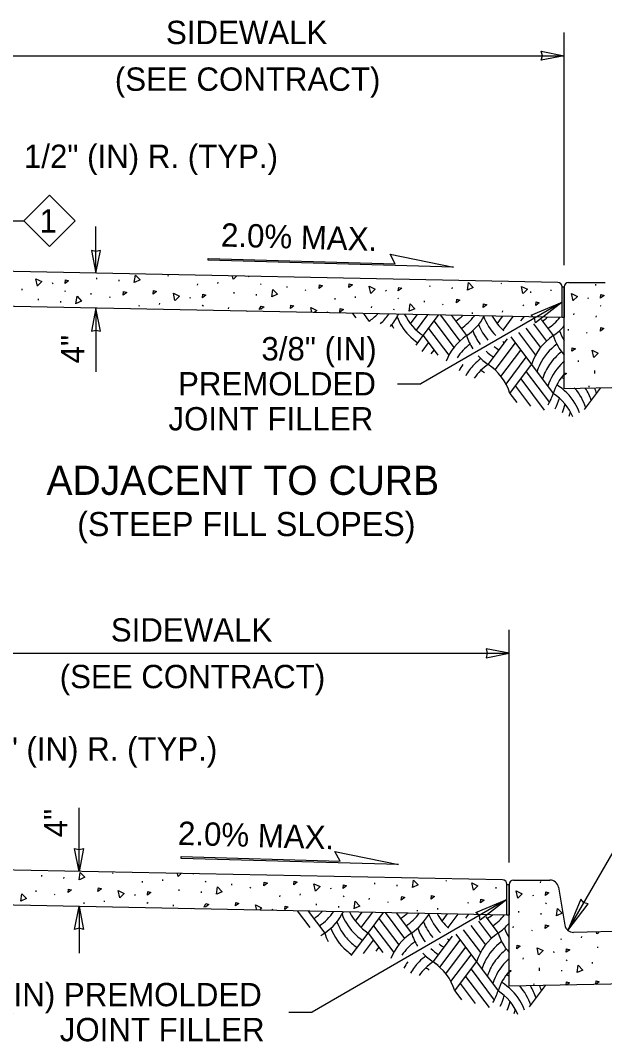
# Model space of a CAD drawing. Extents: x 99862 to 103151, y 100000 to 102076.
# Drawn here: x 100381 to 100781, y 100969 to 101669 of the extents above; entities that cross this region are included whole.
import ezdxf

# ---------------------------------------------------------------- set-up
doc = ezdxf.new("R2010")
doc.units = 0
for name, color, linetype in [('Level 13', 7, 'Continuous'), ('Level 15', 7, 'Continuous'), ('Level 16', 7, 'Continuous'), ('Level 20', 7, 'Continuous'), ('Level 34', 7, 'Continuous'), ('Level 6', 7, 'Continuous')]:
    doc.layers.add(name, color=color, linetype=linetype)

msp = doc.modelspace()

# ---------------------------------------------------------------- linework, layer by layer
at = {"layer": 'Level 13'}
for p, q in [((100433.45, 101491.66), (100433.51, 101492.53)), ((100448.71, 101490.21), (100448.78, 101491.08)), ((100481.98, 101494.1), (100482.5, 101493.72)), ((100537.22, 101493.5), (100537.42, 101493.09)), ((100382.36, 101484.02), (100382.42, 101484.9)), ((100402.96, 101489.15), (100403.32, 101488.43)), ((100411.41, 101483.64), (100411.93, 101483.26)), ((100502.53, 101487.5), (100502.59, 101488.37)), ((100516.46, 101488.69), (100516.52, 101489.56)), ((100545.52, 101488.3), (100546.04, 101487.93)), ((100563.74, 101485.76), (100563.8, 101486.63)), ((100576.11, 101484.21), (100576.63, 101483.83)), ((100631.19, 101483.93), (100631.55, 101483.21)), ((100661.68, 101486.44), (100661.74, 101487.31)), ((100676.95, 101484.99), (100677.01, 101485.87)), ((100710.22, 101488.88), (100710.74, 101488.5)), ((100730.77, 101482.28), (100730.83, 101483.15)), ((100744.7, 101483.47), (100744.76, 101484.35)), ((100775.22, 101487.29), (100775.28, 101488.17)), ((100393.47, 101477.11), (100393.53, 101477.98)), ((100408.74, 101475.66), (100408.8, 101476.53)), ((100429.64, 101481.09), (100429.7, 101481.96)), ((100442.01, 101479.55), (100442.53, 101479.17)), ((100497.09, 101479.27), (100497.45, 101478.55)), ((100527.58, 101481.77), (100527.64, 101482.65)), ((100542.85, 101480.33), (100542.91, 101481.2)), ((100596.66, 101477.61), (100596.72, 101478.49)), ((100610.59, 101478.81), (100610.65, 101479.68)), ((100639.65, 101478.42), (100640.17, 101478.04)), ((100657.87, 101475.88), (100657.93, 101476.75)), ((100769.78, 101479.07), (100770.13, 101478.35)), ((100462.56, 101472.95), (100462.62, 101473.82)), ((100476.49, 101474.14), (100476.55, 101475.01)), ((100505.55, 101473.76), (100506.06, 101473.38)), ((100505.95, 101473.69), (100506.47, 101473.31)), ((100523.77, 101471.21), (100523.83, 101472.08)), ((100536.14, 101469.67), (100536.35, 101469.51)), ((100591.22, 101469.38), (100591.58, 101468.66)), ((100621.71, 101471.89), (100621.77, 101472.76)), ((100636.98, 101470.44), (100637.04, 101471.32)), ((100670.25, 101474.33), (100670.76, 101473.95)), ((100711.43, 101468.93), (100711.49, 101469.8)), ((100725.33, 101474.05), (100725.68, 101473.33)), ((100778.23, 101473.56), (100778.75, 101473.18)), ((100690.8, 101467.73), (100690.86, 101468.6)), ((100760.29, 101467.03), (100760.35, 101467.9)), ((100775.56, 101465.58), (100775.62, 101466.45)), ((100756.48, 101456.46), (100756.54, 101457.33)), ((100768.86, 101454.92), (100769.37, 101454.54)), ((100763.36, 101434.96), (100763.42, 101435.83)), ((100774.48, 101426.97), (100774.54, 101428.92)), ((100770.67, 101417.48), (100770.73, 101418.35)), ((100444.22, 101084.59), (100444.74, 101084.21)), ((100499.46, 101083.99), (100499.66, 101083.59)), ((100395.69, 101082.15), (100395.75, 101083.03)), ((100410.95, 101080.71), (100411.02, 101081.58)), ((100464.77, 101077.99), (100464.83, 101078.86)), ((100478.7, 101079.19), (100478.76, 101080.06)), ((100507.76, 101078.8), (100508.28, 101078.42)), ((100525.98, 101076.25), (100526.04, 101077.13)), ((100623.92, 101076.94), (100623.98, 101077.81)), ((100672.46, 101079.38), (100672.98, 101079)), ((100737.46, 101077.79), (100737.52, 101078.66)), ((100391.88, 101071.59), (100391.94, 101072.46)), ((100404.25, 101070.04), (100404.77, 101069.66)), ((100459.33, 101069.76), (100459.69, 101069.04)), ((100489.82, 101072.27), (100489.88, 101073.14)), ((100505.09, 101070.82), (100505.15, 101071.7)), ((100538.36, 101074.71), (100538.87, 101074.33)), ((100572.83, 101069.3), (100572.89, 101070.18)), ((100593.44, 101074.43), (100593.79, 101073.71)), ((100639.19, 101075.49), (100639.25, 101076.36)), ((100706.94, 101073.97), (100707, 101074.84)), ((100424.8, 101063.44), (100424.86, 101064.32)), ((100438.73, 101064.64), (100438.79, 101065.51)), ((100467.79, 101064.25), (100468.3, 101063.87)), ((100468.19, 101064.18), (100468.71, 101063.8)), ((100558.9, 101068.11), (100558.96, 101068.98)), ((100583.95, 101062.39), (100584.01, 101063.26)), ((100602.29, 101068.85), (100602.81, 101068.47)), ((100620.11, 101066.37), (100620.17, 101067.24)), ((100632.49, 101064.83), (100633, 101064.45)), ((100687.57, 101064.55), (100687.92, 101063.83)), ((100732.02, 101069.56), (100732.37, 101068.84)), ((100740.87, 101063.98), (100741.39, 101063.6)), ((100486.01, 101061.71), (100486.07, 101062.58)), ((100498.38, 101060.16), (100498.59, 101060.01)), ((100553.46, 101059.88), (100553.82, 101059.16)), ((100599.22, 101060.94), (100599.28, 101061.81)), ((100653.04, 101058.23), (100653.1, 101059.1)), ((100666.96, 101059.42), (100667.03, 101060.29)), ((100722.53, 101057.52), (100722.59, 101058.39)), ((100737.8, 101056.07), (100737.86, 101056.95)), ((100718.72, 101046.96), (100718.78, 101047.83)), ((100731.1, 101045.41), (100731.61, 101045.03)), ((100751.64, 101038.81), (100751.7, 101039.68)), ((100765.57, 101040.01), (100765.63, 101040.88)), ((100746.2, 101030.58), (100746.56, 101029.86)), ((100776.69, 101033.09), (100776.75, 101033.96)), ((100725.6, 101025.46), (100725.66, 101026.33)), ((100755.06, 101025), (100755.58, 101024.62)), ((100772.88, 101022.53), (100772.94, 101023.4)), ((100736.72, 101017.47), (100736.78, 101019.41)), ((100751.99, 101017.09), (100752.05, 101017.97)), ((100732.91, 101007.98), (100732.97, 101008.85))]:
    msp.add_line(p, q, dxfattribs=at)
for points in [[(100392.82, 101486.86), (100391.75, 101491.87), (100395.86, 101489.87), (100392.89, 101486.91)], [(100411.76, 101488.68), (100412, 101491.13), (100414.12, 101490.48), (100411.76, 101488.68)], [(100459.16, 101489.29), (100459.87, 101494.36), (100463.05, 101491.08), (100459.25, 101489.32)], [(100526.93, 101491.52), (100526.46, 101493.71)], [(100529.08, 101493.66), (100526.99, 101491.58)], [(100451.56, 101480.57), (100451.8, 101483.02), (100453.93, 101482.37), (100451.56, 101480.57)], [(100472.03, 101481.26), (100472.27, 101483.71), (100474.39, 101483.07), (100472.03, 101481.26)], [(100553.3, 101479.41), (100554, 101484.48), (100557.18, 101481.2), (100553.38, 101479.44)], [(100585.67, 101485.23), (100585.91, 101487.68), (100588.03, 101487.04), (100585.67, 101485.23)], [(100606.13, 101485.93), (100606.37, 101488.38), (100608.5, 101487.73), (100606.13, 101485.93)], [(100621.06, 101481.64), (100619.98, 101486.65), (100624.1, 101484.65), (100621.13, 101481.7)], [(100639.99, 101483.46), (100640.23, 101485.91), (100642.36, 101485.27), (100639.99, 101483.46)], [(100687.4, 101484.07), (100688.1, 101489.15), (100691.28, 101485.86), (100687.48, 101484.1)], [(100725.33, 101481.61), (100724.26, 101486.62), (100728.37, 101484.62), (100725.4, 101481.67)], [(100419.19, 101474.74), (100419.9, 101479.81), (100423.08, 101476.53), (100419.27, 101474.77)], [(100486.95, 101476.97), (100485.88, 101481.98), (100489.99, 101479.99), (100487.02, 101477.03)], [(100505.89, 101478.79), (100506.13, 101481.24), (100508.25, 101480.6), (100505.89, 101478.79)], [(100679.8, 101475.35), (100680.04, 101477.8), (100682.16, 101477.16), (100679.8, 101475.35)], [(100734.12, 101473.58), (100734.37, 101476.03), (100736.49, 101475.38), (100734.12, 101473.58)], [(100759.64, 101476.77), (100758.57, 101481.78), (100762.68, 101479.78), (100759.71, 101476.83)], [(100778.57, 101478.59), (100778.81, 101481.04), (100780.94, 101480.4), (100778.57, 101478.59)], [(100544.66, 101470.68), (100545.94, 101473.14), (100548.06, 101472.49), (100545.69, 101470.68)], [(100566.16, 101471.38), (100566.4, 101473.83), (100568.52, 101473.18), (100566.16, 101471.38)], [(100580.76, 101468.62), (100580.01, 101472.1), (100584.12, 101470.1), (100582.6, 101468.59)], [(100600.02, 101468.91), (100600.26, 101471.36), (100602.39, 101470.72), (100600.02, 101468.91)], [(100647.43, 101469.52), (100648.13, 101474.6), (100651.31, 101471.31), (100647.51, 101469.55)], [(100698.17, 101472.23), (100698.42, 101474.68), (100700.54, 101474.04), (100698.17, 101472.23)], [(100778.41, 101455.94), (100778.65, 101458.39), (100780.77, 101457.74), (100778.41, 101455.94)], [(100758.9, 101442.08), (100759.14, 101444.53), (100761.26, 101443.89), (100758.9, 101442.08)], [(100773.83, 101437.79), (100772.75, 101442.8), (100776.86, 101440.8), (100773.89, 101437.85)], [(100753.65, 101427.33), (100755.15, 101426.87), (100753.65, 101425.72)], [(100421.4, 101079.78), (100422.11, 101084.86), (100425.29, 101081.58), (100421.49, 101079.81)], [(100489.17, 101082.02), (100488.7, 101084.21)], [(100491.32, 101084.15), (100489.24, 101082.07)], [(100547.91, 101075.73), (100548.15, 101078.18), (100550.27, 101077.54), (100547.91, 101075.73)], [(100568.37, 101076.42), (100568.61, 101078.87), (100570.74, 101078.23), (100568.37, 101076.42)], [(100583.3, 101072.14), (100582.22, 101077.15), (100586.34, 101075.15), (100583.37, 101072.19)], [(100649.64, 101074.57), (100650.34, 101079.64), (100653.52, 101076.36), (100649.72, 101074.6)], [(100691.52, 101072.74), (100690.44, 101077.75), (100694.55, 101075.75), (100691.59, 101072.79)], [(100381.43, 101065.24), (100382.14, 101070.31), (100385.32, 101067.03), (100381.51, 101065.27)], [(100413.8, 101071.06), (100414.04, 101073.51), (100416.17, 101072.87), (100413.8, 101071.06)], [(100434.27, 101071.76), (100434.51, 101074.21), (100436.63, 101073.56), (100434.27, 101071.76)], [(100449.2, 101067.47), (100448.12, 101072.48), (100452.23, 101070.48), (100449.26, 101067.53)], [(100468.13, 101069.29), (100468.37, 101071.74), (100470.49, 101071.1), (100468.13, 101069.29)], [(100515.54, 101069.9), (100516.24, 101074.98), (100519.42, 101071.69), (100515.62, 101069.93)], [(100602.23, 101073.96), (100602.47, 101076.41), (100604.6, 101075.76), (100602.23, 101073.96)], [(100721.88, 101067.27), (100720.81, 101072.28), (100724.92, 101070.28), (100721.95, 101067.33)], [(100740.81, 101069.09), (100741.05, 101071.54), (100743.18, 101070.9), (100740.81, 101069.09)], [(100506.9, 101061.18), (100508.18, 101063.63), (100510.3, 101062.99), (100507.93, 101061.18)], [(100528.4, 101061.87), (100528.64, 101064.32), (100530.76, 101063.68), (100528.4, 101061.87)], [(100609.67, 101060.02), (100610.37, 101065.09), (100613.55, 101061.81), (100609.75, 101060.05)], [(100642.04, 101065.85), (100642.28, 101068.3), (100644.41, 101067.65), (100642.04, 101065.85)], [(100662.5, 101066.54), (100662.74, 101068.99), (100664.87, 101068.35), (100662.5, 101066.54)], [(100696.36, 101064.07), (100696.61, 101066.52), (100698.73, 101065.88), (100696.36, 101064.07)], [(100543, 101059.12), (100542.25, 101062.6), (100546.36, 101060.6), (100544.84, 101059.08)], [(100562.26, 101059.41), (100562.5, 101061.86), (100564.63, 101061.21), (100562.26, 101059.41)], [(100748.25, 101055.15), (100748.95, 101060.23), (100752.13, 101056.94), (100748.33, 101055.18)], [(100740.65, 101046.43), (100740.89, 101048.88), (100743.01, 101048.24), (100740.65, 101046.43)], [(100776.04, 101042.84), (100775.77, 101044.11)], [(100777.36, 101044.14), (100776.11, 101042.89)], [(100721.14, 101032.58), (100721.38, 101035.03), (100723.51, 101034.38), (100721.14, 101032.58)], [(100736.07, 101028.29), (100734.99, 101033.3), (100739.1, 101031.3), (100736.14, 101028.35)], [(100755, 101030.11), (100755.24, 101032.56), (100757.37, 101031.92), (100755, 101030.11)], [(100762.44, 101016.17), (100763.14, 101021.25), (100766.32, 101017.96), (100762.52, 101016.2)], [(100715.89, 101017.82), (100717.39, 101017.37), (100715.89, 101016.22)], [(100754.86, 101007.69), (100755.08, 101009.9), (100757.2, 101009.26), (100755.16, 101007.7)], [(100775.3, 101008.14), (100775.54, 101010.6), (100777.66, 101009.95), (100775.3, 101008.14)]]:
    msp.add_lwpolyline(points, dxfattribs=at)
at = {"layer": 'Level 15'}
for p, q in [((100753.65, 101501.2), (100753.65, 101660.69)), ((100322.4, 101644.67), (100753.65, 101644.67)), ((100367.51, 101531.52), (100383.51, 101531.52)), ((100432.85, 101495.58), (100432.85, 101527.58)), ((100752.15, 101475.72), (100655.37, 101419.85)), ((100432.85, 101471.58), (100432.85, 101427.98)), ((100639.37, 101419.85), (100655.37, 101419.85)), ((100715.89, 101091.69), (100715.89, 101251.18)), ((100284.64, 101235.17), (100715.89, 101235.17)), ((100421.33, 101085.56), (100421.33, 101129.16)), ((100756.12, 101045.18), (100802.54, 101125.58)), ((100714.39, 101066.22), (100580.92, 100989.16)), ((100421.32, 101061.56), (100421.32, 101029.56)), ((100564.92, 100989.16), (100580.92, 100989.16))]:
    msp.add_line(p, q, dxfattribs=at)
for points in [[(100753.65, 101644.67), (100737.93, 101641.59), (100738.65, 101644.67), (100737.93, 101647.76)], [(100432.84, 101495.58), (100435.93, 101511.31), (100432.84, 101510.58), (100429.76, 101511.31)], [(100752.15, 101475.72), (100733.87, 101461.72), (100733.29, 101464.84), (100730.89, 101466.89)], [(100432.85, 101471.58), (100429.76, 101455.86), (100432.85, 101456.59), (100435.93, 101455.86)], [(100715.89, 101235.17), (100700.16, 101238.25), (100700.89, 101235.17), (100700.16, 101232.08)], [(100421.32, 101085.56), (100418.24, 101101.28), (100421.32, 101100.55), (100424.41, 101101.28)], [(100714.39, 101066.22), (100696.11, 101052.22), (100695.53, 101055.33), (100693.13, 101057.39)], [(100756.12, 101045.18), (100770.12, 101063.46), (100767.01, 101064.03), (100764.95, 101066.44)], [(100421.32, 101061.56), (100424.41, 101045.83), (100421.32, 101046.56), (100418.24, 101045.83)]]:
    msp.add_lwpolyline(points, close=True, dxfattribs=at)
at = {"layer": 'Level 16'}
for points in [[(100752.15, 101486.2), (100753.65, 101486.2), (100753.65, 101465.2), (100752.15, 101465.2)], [(100714.39, 101076.69), (100715.89, 101076.69), (100715.89, 101055.69), (100714.39, 101055.69)]]:
    msp.add_lwpolyline(points, close=True, dxfattribs=at)
at = {"layer": 'Level 20'}
for points in [[(100401.07, 101549.08), (100418.62, 101531.52), (100401.07, 101513.97), (100383.51, 101531.52)], [(100509.82, 101505.81), (100637.87, 101502.11), (100634.32, 101508.7), (100677.83, 101499.72), (100509.78, 101504.58)], [(100491.19, 101095.76), (100600.11, 101092.61), (100596.56, 101099.19), (100640.07, 101090.22), (100491.15, 101094.52)]]:
    msp.add_lwpolyline(points, close=True, dxfattribs=at)
at = {"layer": 'Level 34'}
for p, q in [((100608.5, 101468.07), (100610.8, 101465)), ((100616.04, 101467.92), (100619.83, 101462.87)), ((100648.3, 101461.01), (100652.93, 101467.18)), ((100652.38, 101456.55), (100660.24, 101467.04)), ((100657.03, 101452.85), (100667.56, 101466.89)), ((100664.46, 101462.75), (100678, 101444.7)), ((100668.8, 101466.86), (100682.08, 101449.16)), ((100676.34, 101466.71), (100686.73, 101452.85)), ((100707.7, 101461.01), (100711.45, 101466.01)), ((100711.77, 101456.55), (100718.76, 101465.86)), ((100723.98, 101462.93), (100726.08, 101465.72)), ((100737.79, 101463.97), (100746.13, 101452.85)), ((100660.75, 101457.8), (100674.56, 101439.39)), ((100722.25, 101455), (100733.95, 101439.39)), ((100727.43, 101457.99), (100737.4, 101444.7)), ((100732.61, 101460.98), (100741.47, 101449.16)), ((100652.2, 101446.41), (100657.03, 101452.85)), ((100656.3, 101441.98), (100660.75, 101447.91)), ((100657.03, 101452.85), (100667.14, 101439.38)), ((100701.58, 101433.05), (100714.82, 101450.71)), ((100706.23, 101429.36), (100720.14, 101447.9)), ((100717.07, 101452.01), (100731.28, 101433.06)), ((100662.55, 101440.42), (100664.46, 101442.96)), ((100710.31, 101424.9), (100723.85, 101442.95)), ((100713.76, 101419.59), (100727.57, 101438)), ((100716.43, 101413.26), (100731.28, 101433.05)), ((100727.57, 101428.11), (100743.46, 101406.92)), ((100731.28, 101433.06), (100746.13, 101413.26)), ((100723.86, 101423.16), (100739.92, 101401.74)), ((100716.44, 101413.26), (100721.12, 101407.01)), ((100720.15, 101418.21), (100730.41, 101404.52)), ((100767.61, 101402.31), (100775.83, 101413.26)), ((100775.83, 101413.26), (100778.57, 101416.92)), ((100570.74, 101058.57), (100579.35, 101047.09)), ((100578.28, 101058.42), (100589.58, 101043.35)), ((100610.54, 101051.51), (100615.17, 101057.68)), ((100614.62, 101047.04), (100622.48, 101057.53)), ((100619.27, 101043.35), (100629.8, 101057.38)), ((100631.04, 101057.36), (100644.32, 101039.66)), ((100638.58, 101057.21), (100648.97, 101043.35)), ((100669.94, 101051.51), (100673.69, 101056.51)), ((100674.02, 101047.04), (100681, 101056.36)), ((100686.22, 101053.42), (100688.32, 101056.21)), ((100626.7, 101053.25), (100640.24, 101035.19)), ((100694.85, 101051.48), (100703.71, 101039.66)), ((100700.03, 101054.47), (100708.37, 101043.35)), ((100607.68, 101027.89), (100619.27, 101043.35)), ((100619.27, 101043.35), (100629.38, 101029.88)), ((100622.99, 101048.3), (100636.8, 101029.89)), ((100679.31, 101042.5), (100693.52, 101023.55)), ((100684.49, 101045.49), (100696.19, 101029.89)), ((100689.67, 101048.48), (100699.64, 101035.19)), ((100616.24, 101029.4), (100622.99, 101038.4)), ((100663.82, 101023.55), (100677.06, 101041.2)), ((100668.48, 101019.86), (100682.38, 101038.4)), ((100624.79, 101030.91), (100626.7, 101033.45)), ((100672.55, 101015.39), (100686.09, 101033.45)), ((100676, 101010.08), (100689.81, 101028.5)), ((100678.67, 101003.75), (100693.52, 101023.55)), ((100693.52, 101023.55), (100708.37, 101003.75)), ((100689.81, 101018.6), (100705.7, 100997.42)), ((100682.39, 101008.7), (100692.65, 100995.02)), ((100686.1, 101013.65), (100702.16, 100992.23)), ((100738.07, 101003.75), (100740.81, 101007.41)), ((100678.68, 101003.75), (100683.37, 100997.5)), ((100729.85, 100992.8), (100738.07, 101003.75))]:
    msp.add_line(p, q, dxfattribs=at)
for centre, start, end in [((100598.95, 101493.94), 303.90361, 315.75237), ((100602.66, 101488.99), 311.83361, 325.24141), ((100606.37, 101484.04), 318.61621, 333.77581), ((100674.28, 101479.09), 200.87781, 211.33197), ((100677.99, 101484.04), 206.36846, 236.09639), ((100658.35, 101493.94), 303.90361, 313.21892), ((100662.06, 101488.99), 303.90361, 323.03823), ((100665.77, 101484.04), 303.90361, 331.76223), ((100733.68, 101479.09), 199.94587, 224.0978), ((100737.39, 101484.04), 208.43007, 227.95518), ((100717.74, 101493.94), 303.90361, 310.56526), ((100721.45, 101488.99), 303.90361, 320.77209), ((100670.57, 101474.14), 201.43438, 205.44713), ((100674.28, 101479.09), 211.33188, 236.09639), ((100726.26, 101469.19), 200.24322, 216.55794), ((100729.97, 101474.14), 201.43438, 220.3049), ((100725.17, 101484.04), 303.90361, 319.2878), ((100785.65, 101469.19), 200.24322, 211.61888), ((100707.69, 101421.67), 123.90361, 158.72507), ((100722.54, 101464.24), 197.6434, 212.83994), ((100733.68, 101479.09), 233.78139, 236.09639), ((100767.09, 101421.67), 123.90361, 162.3566), ((100781.94, 101464.24), 197.6434, 221.1697), ((100711.4, 101416.72), 126.30625, 146.15458), ((100726.26, 101469.19), 225.89517, 236.09368), ((100729.97, 101474.14), 229.78975, 236.09639), ((100770.8, 101416.72), 126.30625, 154.2266), ((100774.51, 101411.77), 127.1006, 145.49109), ((100718.83, 101406.82), 126.331, 135.71278), ((100722.54, 101464.24), 222.07643, 236.09645), ((100722.54, 101464.24), 222.07643, 236.09645), ((100778.23, 101406.82), 130.84176, 135.71278), ((100715.12, 101411.77), 145.49102, 153.1583), ((100718.83, 101406.82), 135.71269, 150.41204), ((100722.54, 101401.87), 123.90361, 144.38269), ((100676.91, 101396.92), 54.12975, 58.54646), ((100680.62, 101401.87), 49.65764, 56.09634), ((100680.62, 101401.87), 17.6434, 56.09634), ((100770.8, 101416.72), 154.22654, 162.3566), ((100774.51, 101411.77), 145.49102, 162.3566), ((100778.23, 101406.82), 135.71269, 162.3566), ((100781.94, 101401.87), 138.8303, 162.3566), ((100732.59, 101391.97), 56.30046, 59.30215), ((100710.32, 101424.65), 329.02899, 342.3566), ((100725.17, 101382.07), 23.54417, 56.09639), ((100728.88, 101387.02), 31.33163, 58.48737), ((100732.59, 101391.97), 40.94134, 41.44048), ((100732.59, 101391.97), 17.6434, 40.94141), ((100736.3, 101396.92), 17.6434, 31.78143), ((100740.02, 101401.87), 17.6434, 23.47063), ((100714.03, 101419.7), 333.0258, 345.01126), ((100717.74, 101414.75), 337.02798, 346.31988), ((100728.88, 101387.02), 20.26046, 31.33172), ((100721.45, 101409.8), 341.05532, 345.77133), ((100561.19, 101084.44), 303.90361, 315.75237), ((100564.9, 101079.49), 303.90361, 325.24141), ((100568.62, 101074.54), 303.90361, 333.77581), ((100636.52, 101069.59), 200.87781, 211.33197), ((100640.23, 101074.54), 206.36846, 236.09639), ((100620.59, 101084.44), 303.90361, 313.21892), ((100624.3, 101079.49), 303.90361, 323.03823), ((100628.01, 101074.54), 303.90361, 331.76223), ((100695.92, 101069.59), 199.94587, 224.0978), ((100699.63, 101074.54), 208.43007, 227.95518), ((100679.98, 101084.44), 303.90361, 310.56526), ((100683.69, 101079.49), 303.90361, 320.77209), ((100632.81, 101064.64), 201.43438, 220.94161), ((100636.52, 101069.59), 211.33188, 236.09639), ((100692.21, 101064.64), 201.43438, 220.3049), ((100687.41, 101074.54), 303.90361, 319.2878), ((100610.54, 101012.16), 123.90361, 128.99779), ((100625.39, 101054.74), 197.6434, 207.3316), ((100629.1, 101059.69), 200.24322, 228.95992), ((100669.93, 101012.16), 123.90361, 158.72507), ((100684.78, 101054.74), 197.6434, 212.83994), ((100688.5, 101059.69), 200.24322, 216.55794), ((100729.33, 101012.16), 123.90361, 162.3566), ((100744.18, 101054.74), 197.6434, 221.1697), ((100747.89, 101059.69), 200.24322, 211.61888), ((100614.25, 101007.21), 126.30625, 126.31242), ((100632.81, 101064.64), 220.94154, 236.09639), ((100673.64, 101007.21), 126.30625, 146.15458), ((100692.21, 101064.64), 229.78975, 236.09639), ((100695.92, 101069.59), 233.78139, 236.09639), ((100733.04, 101007.21), 126.30625, 154.2266), ((100629.1, 101059.69), 228.95986, 236.09639), ((100684.78, 101054.74), 222.07643, 236.09645), ((100684.78, 101054.74), 222.07643, 236.09645), ((100688.5, 101059.69), 225.89517, 236.09368), ((100736.75, 101002.26), 127.1006, 145.49109), ((100677.36, 101002.26), 145.49102, 153.1583), ((100681.07, 100997.31), 135.71269, 150.41204), ((100681.07, 100997.31), 126.331, 135.71278), ((100684.78, 100992.36), 123.90361, 144.38269), ((100642.86, 100992.36), 49.65764, 56.09634), ((100642.86, 100992.36), 17.6434, 56.09634), ((100733.04, 101007.21), 154.22654, 162.3566), ((100736.75, 101002.26), 145.49102, 162.3566), ((100740.47, 100997.31), 135.71269, 162.3566), ((100740.47, 100997.31), 130.84176, 135.71278), ((100639.15, 100987.41), 54.12975, 58.54646), ((100744.18, 100992.36), 138.8303, 162.3566), ((100694.83, 100982.46), 55.9156, 59.30215), ((100691.12, 100977.51), 31.33163, 58.48737), ((100694.83, 100982.46), 17.6434, 40.88516), ((100698.54, 100987.41), 17.6434, 31.78143), ((100702.26, 100992.36), 17.6434, 23.47063), ((100672.56, 101015.14), 329.02899, 342.3566), ((100687.41, 100972.56), 23.54417, 56.09639), ((100676.27, 101010.19), 333.0258, 345.01126), ((100679.98, 101005.24), 337.02798, 346.31988), ((100691.12, 100977.51), 20.26046, 31.33172), ((100683.69, 101000.29), 341.05532, 345.77133)]:
    msp.add_arc(centre, 37.58, start, end, dxfattribs=at)
at = {"layer": 'Level 6'}
for p, q in [((100749.21, 101489.26), (100325.46, 101497.73)), ((100752.15, 101465.2), (100752.15, 101486.26)), ((100753.65, 101416.42), (100753.65, 101486.2)), ((100756.65, 101489.2), (100781.57, 101489.2)), ((100752.15, 101465.2), (100322.4, 101473.79)), ((100861.65, 101418.58), (100753.65, 101416.42)), ((100711.45, 101079.75), (100287.7, 101088.23)), ((100714.39, 101055.69), (100714.39, 101076.75)), ((100715.89, 101006.91), (100715.89, 101076.69)), ((100718.89, 101079.69), (100743.81, 101079.69)), ((100749.73, 101074.68), (100754.04, 101048.81)), ((100714.39, 101055.69), (100284.64, 101064.29)), ((100820.83, 101045.01), (100760.08, 101043.8)), ((100823.89, 101009.07), (100715.89, 101006.91))]:
    msp.add_line(p, q, dxfattribs=at)
for centre, radius, start, end in [((100749.15, 101486.26), 3, 360, 88.85424), ((100756.65, 101486.2), 3, 90, 180), ((100711.39, 101076.75), 3, 360, 88.85424), ((100718.89, 101076.69), 3, 90, 180), ((100743.81, 101073.69), 6, 9.46232, 90), ((100759.96, 101049.8), 6, 189.46232, 271.14576)]:
    msp.add_arc(centre, radius, start, end, dxfattribs=at)

# ---------------------------------------------------------------- texts
at = {"layer": 'Level 20'}
for s, height, p in [('SIDEWALK', 16, (100480.82, 101652.67)), ('(SEE CONTRACT)', 16, (100445.82, 101620.67)), ('1/2" (IN) R. (TYP.)', 16, (100383.53, 101567.76)), ('1', 16, (100394.2, 101523.52)), (' 3/8" (IN) ', 16, (100540.27, 101435.85)), ('PREMOLDED', 16, (100489.11, 101411.85)), ('JOINT FILLER', 16, (100482.53, 101387.85)), ('ADJACENT TO CURB', 20, (100398.98, 101343.69)), ('(STEEP FILL SLOPES)', 16.5, (100420.02, 101315.44)), ('SIDEWALK', 16, (100443.06, 101243.17)), ('(SEE CONTRACT)', 16, (100408.06, 101211.17)), ('1/2" (IN) R. (TYP.)', 16, (100341.97, 101161.56)), ('3/8" (IN) PREMOLDED', 16, (100326.05, 100993.16)), ('JOINT FILLER', 16, (100408.08, 100969.16))]:
    msp.add_text(s, height=height, dxfattribs=at).set_placement(p)
for s, rotation, p in [('2.0% MAX.', 358.34451, (100518.33, 101513.96)), ('4"', 90, (100424.85, 101433.82)), ('4"', 90, (100413.33, 101108.97)), ('2.0% MAX.', 358.34451, (100488.85, 101103.83))]:
    msp.add_text(s, height=16, rotation=rotation, dxfattribs=at).set_placement(p)

doc.saveas('drawing.dxf')
